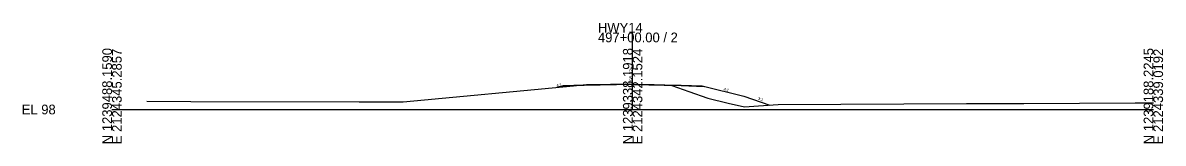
# Model space of a CAD drawing. Extents: x -26 to 303, y -10 to 11521.
# Drawn here: x -25.7 to 302.8, y 8490.3 to 8524.9 of the extents above; entities that cross this region are included whole.
import ezdxf

# ---------------------------------------------------------------- set-up
doc = ezdxf.new("R2010")
doc.units = 0
for name, color, linetype in [('XS_CELL', 7, 'Continuous'), ('XS_P_FINISHED_GRADE', 7, 'Continuous'), ('XS_P_SUBGRADE_GRANULAR', 7, 'Continuous'), ('XS_P_SUBGRADE_LEVELING', 7, 'Continuous'), ('XS_P_TX_FS_BS', 7, 'Continuous'), ('XS_X_GROUND', 7, 'Continuous'), ('XS_X_GROUND_TX', 7, 'Continuous')]:
    doc.layers.add(name, color=color, linetype=linetype)

msp = doc.modelspace()

# ---------------------------------------------------------------- linework, layer by layer
at = {"layer": 'XS_CELL'}
for p, q in [((150, 8500), (150, 8522.14)), ((0, 8500), (150, 8500)), ((150, 8500), (300, 8500))]:
    msp.add_line(p, q, dxfattribs=at)
at = {"layer": 'XS_P_FINISHED_GRADE'}
for p, q in [((130, 8506.8), (128.23, 8506.36)), ((136, 8507.04), (130, 8506.8)), ((150, 8507.32), (136, 8507.04)), ((150, 8507.32), (164, 8507.04)), ((164, 8507.04), (170, 8506.8)), ((170, 8506.8), (182, 8503.8)), ((182, 8503.8), (189.55, 8501.29))]:
    msp.add_line(p, q, dxfattribs=at)
at = {"layer": 'XS_P_SUBGRADE_GRANULAR'}
for p, q in [((136, 8506.92), (129.4, 8506.65)), ((164, 8506.92), (170.6, 8506.65))]:
    msp.add_line(p, q, dxfattribs=at)
at = {"layer": 'XS_P_SUBGRADE_LEVELING'}
for p, q in [((150, 8507.2), (136, 8506.92)), ((136, 8506.92), (136, 8507.04)), ((150, 8507.2), (164, 8506.92)), ((164, 8506.92), (164, 8507.04))]:
    msp.add_line(p, q, dxfattribs=at)
at = {"layer": 'XS_X_GROUND'}
for p, q in [((83.9, 8502.22), (132.98, 8506.8)), ((132.98, 8506.8), (133.81, 8506.93)), ((133.81, 8506.93), (134.66, 8506.99)), ((134.66, 8506.99), (136.7, 8507.15)), ((136.7, 8507.15), (139.35, 8507.21)), ((139.35, 8507.21), (147.84, 8507.38)), ((147.84, 8507.38), (150, 8507.32)), ((150, 8507.32), (156.24, 8507.15)), ((156.24, 8507.15), (158.34, 8507.09)), ((158.34, 8507.09), (159.11, 8507.04)), ((159.11, 8507.04), (161.25, 8506.88)), ((161.25, 8506.88), (166.17, 8505.16)), ((166.17, 8505.16), (171.66, 8503.29)), ((171.66, 8503.29), (177.56, 8501.86)), ((10.07, 8502.37), (22.71, 8502.33)), ((22.71, 8502.33), (71.21, 8502.24)), ((71.21, 8502.24), (83.9, 8502.22)), ((177.56, 8501.86), (182.23, 8500.81)), ((182.23, 8500.81), (186.28, 8501.06)), ((186.28, 8501.06), (191.89, 8501.45)), ((191.89, 8501.45), (246.14, 8501.69)), ((246.14, 8501.69), (251.38, 8501.74)), ((251.38, 8501.74), (257.91, 8501.72)), ((257.91, 8501.72), (262.72, 8501.74)), ((262.72, 8501.74), (294.76, 8501.88)), ((294.76, 8501.88), (300, 8501.9))]:
    msp.add_line(p, q, dxfattribs=at)

# ---------------------------------------------------------------- texts
at = {"layer": 'XS_CELL'}
for s, p in [('497+00.00 / 2', (140, 8519.34)), ('HWY14', (140, 8522.14)), ('EL 98', (-26, 8498.6))]:
    msp.add_text(s, height=2.8, dxfattribs=at).set_placement(p)
for s, p in [('N 1239488.1590', (0, 8490)), ('E 2124345.2857', (2.8, 8490)), ('N 1239338.1918', (150, 8490)), ('E 2124342.1524', (152.8, 8490)), ('N 1239188.2245', (300, 8490)), ('E 2124339.0192', (302.8, 8490))]:
    msp.add_text(s, height=2.8, rotation=90, dxfattribs=at).set_placement(p)
at = {"layer": 'XS_P_TX_FS_BS'}
for s, rotation, p in [('4:1', 14.0362, (128.15, 8506.45)), ('4:1', 345.9638, (176.14, 8505.5)), ('3:1', 341.5651, (186.02, 8502.83))]:
    msp.add_text(s, height=0.8, rotation=rotation, dxfattribs=at).set_placement(p)
at = {"layer": 'XS_X_GROUND_TX'}
msp.add_text('105.32', height=1, rotation=90, dxfattribs=at).set_placement((150, 8507.42))

doc.saveas('drawing.dxf')
